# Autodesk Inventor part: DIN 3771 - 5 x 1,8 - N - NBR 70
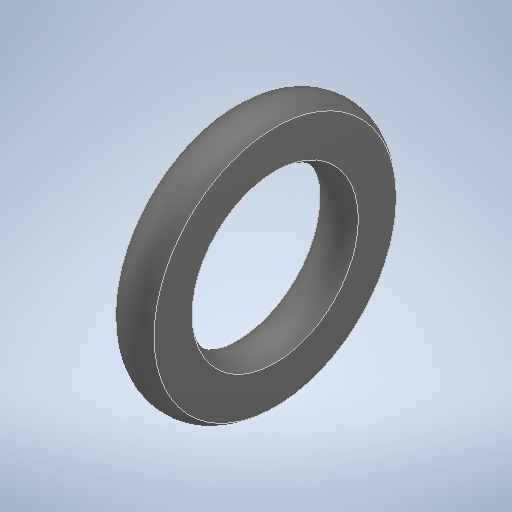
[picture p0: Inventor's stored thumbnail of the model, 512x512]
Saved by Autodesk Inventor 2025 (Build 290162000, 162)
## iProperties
Created: 2020-01
Part Number: DIN 3771 - 5 x 1,8 - N - NBR 70
Material: Rubber
Description: O-Ring
Document SubType Name: Modeling
Designer: Ryzen5700u
Density: 0.93 g/cm^3
Appearance: Default
Author: Ryzen5700u
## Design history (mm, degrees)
feature "Solid1"
node "Solido1"
